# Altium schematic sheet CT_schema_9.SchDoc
size 385 x 278 mm
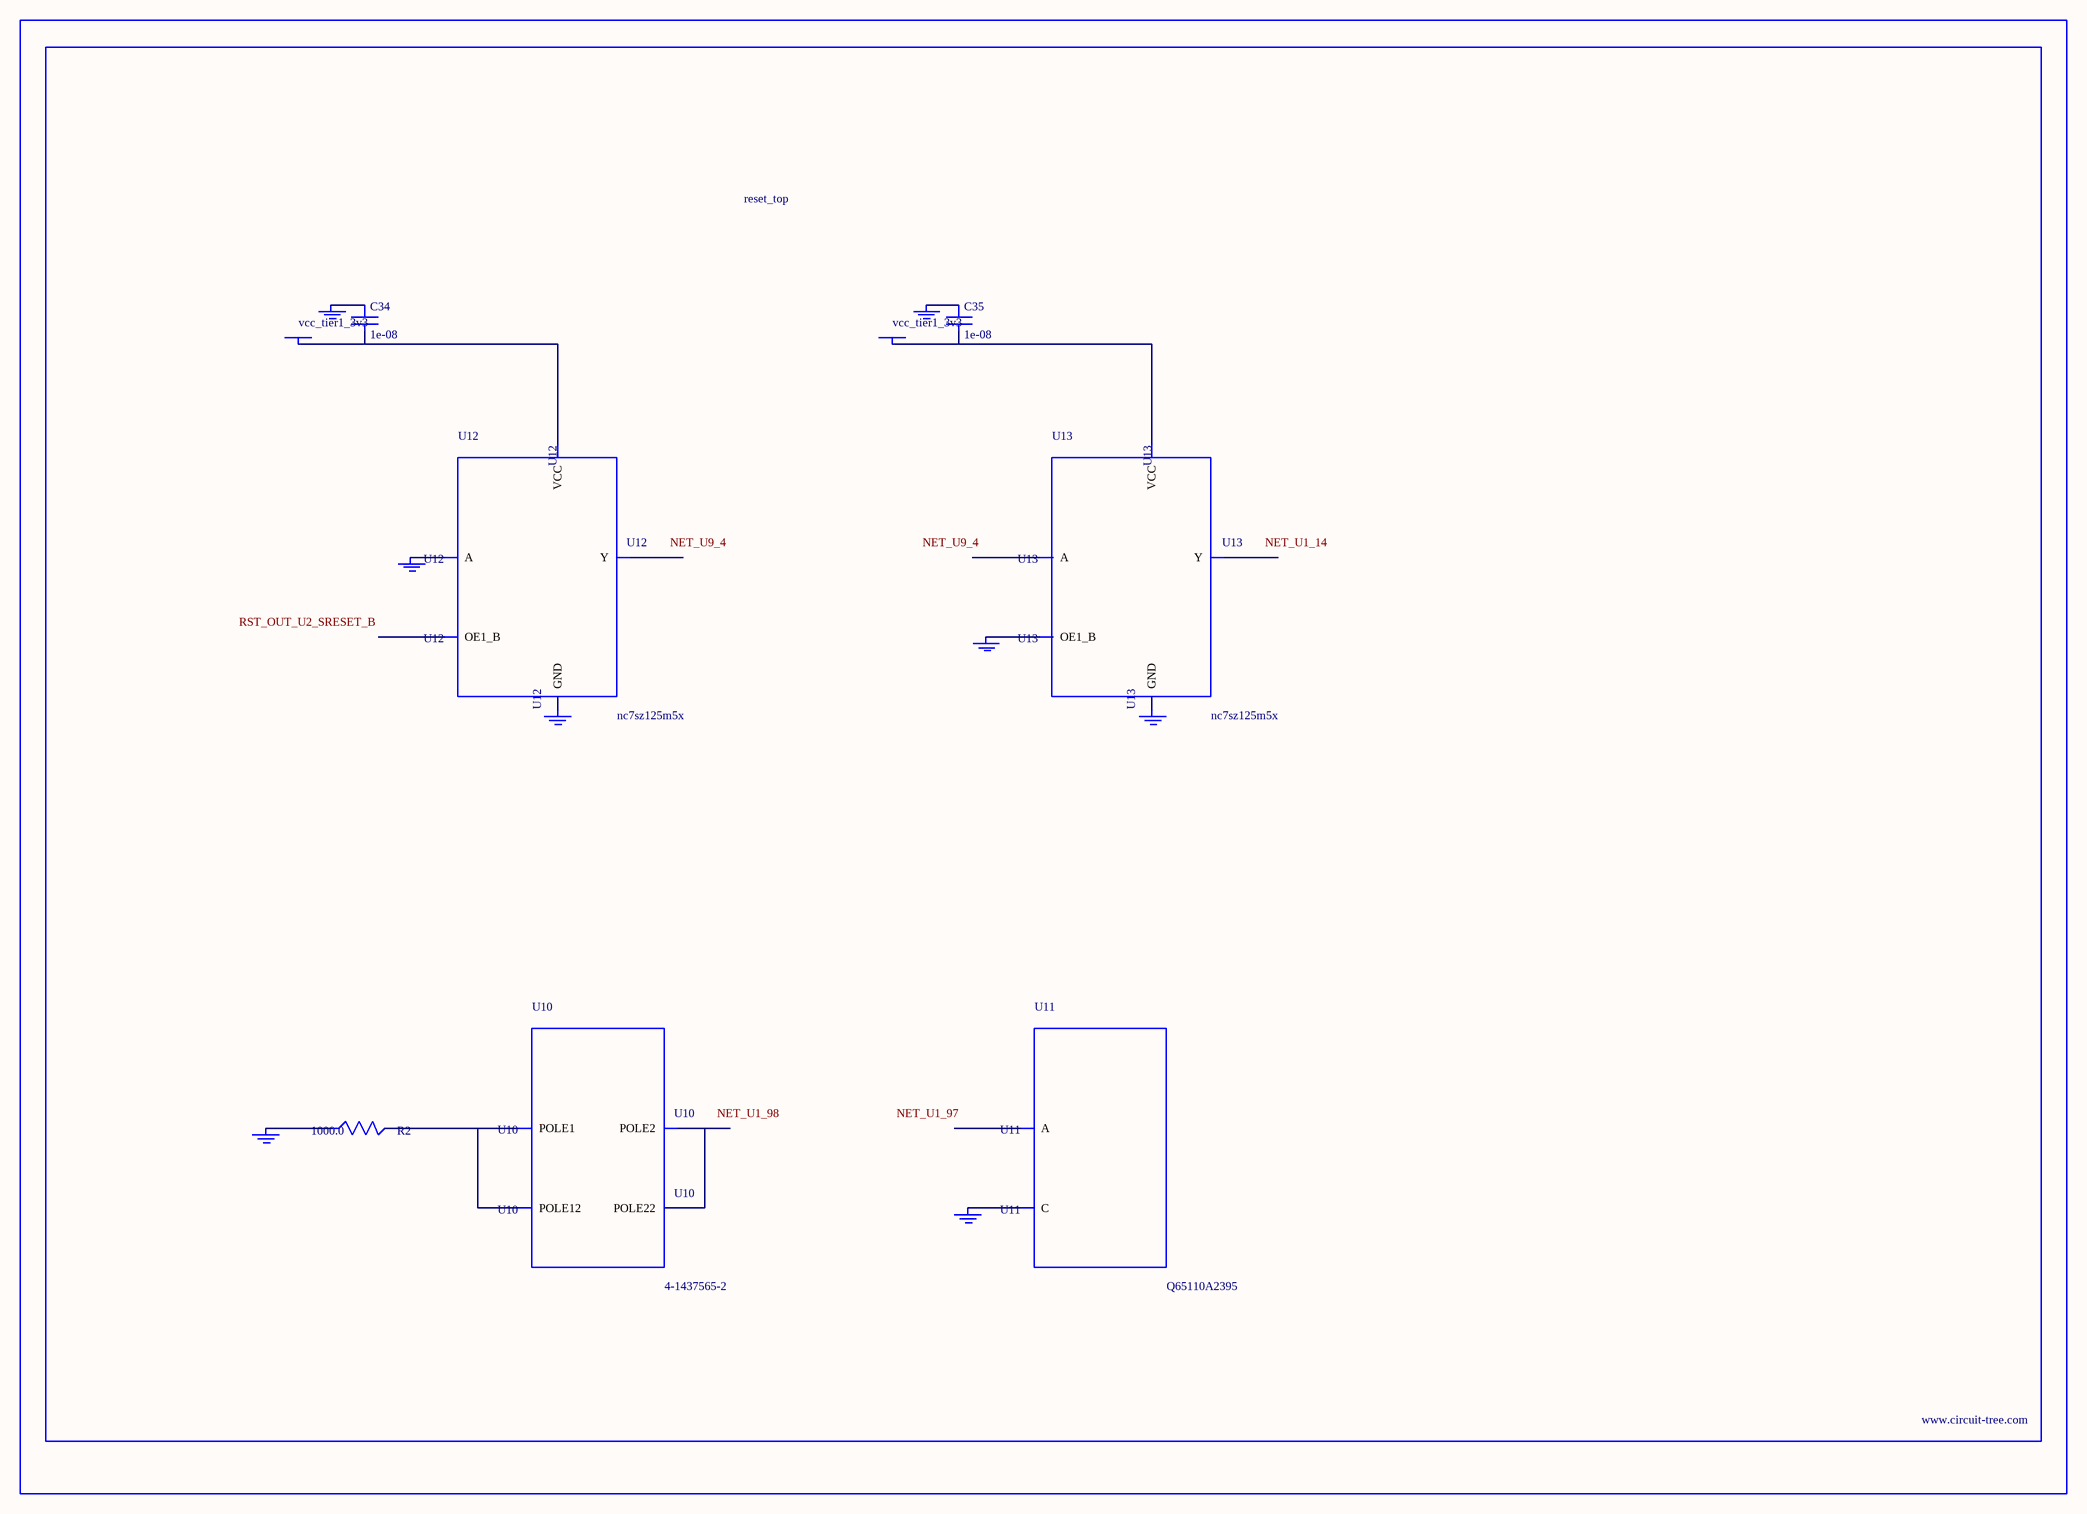
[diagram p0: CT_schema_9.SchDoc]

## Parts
BORDER8  (no value)
C34  1e-08  [C0402]
C35  1e-08  [C0402]
GND_INSTANCE_8_0  (no value)
GND_INSTANCE_8_1  (no value)
GND_INSTANCE_8_2  (no value)
GND_INSTANCE_8_3  (no value)
GND_INSTANCE_8_4  (no value)
GND_INSTANCE_8_5  (no value)
GND_INSTANCE_8_6  (no value)
GND_INSTANCE_8_7  (no value)
POWER_INSTANCE_8_0  vcc_tier1_3v3
POWER_INSTANCE_8_1  vcc_tier1_3v3
R2  1000.0  [R0603]
U10  4-1437565-2  [SW_4-1437565-2]
U11  Q65110A2395  [LGM67K-G1J2-24-Z]
U12  nc7sz125m5x  [NC7SZ125M5X]
U13  nc7sz125m5x  [NC7SZ125M5X]

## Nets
NetC34_1: C34.1 GND_INSTANCE_8_2.0(GND)
NetC34_2: C34.2 POWER_INSTANCE_8_0.0(PWR) U12.5(VCC)
NetC35_1: C35.1 GND_INSTANCE_8_5.0(GND)
NetC35_2: C35.2 POWER_INSTANCE_8_1.0(PWR) U13.5(VCC)
NetGND_INSTANCE_8_0_0: GND_INSTANCE_8_0.0(GND) R2.1
NetGND_INSTANCE_8_1_0: GND_INSTANCE_8_1.0(GND) U11.C
NetGND_INSTANCE_8_3_0: GND_INSTANCE_8_3.0(GND) U12.2(A)
NetGND_INSTANCE_8_4_0: GND_INSTANCE_8_4.0(GND) U12.3(GND)
NetGND_INSTANCE_8_6_0: GND_INSTANCE_8_6.0(GND) U13.1(OE1_B)
NetGND_INSTANCE_8_7_0: GND_INSTANCE_8_7.0(GND) U13.3(GND)
NetR2_2: R2.2 U10.1(POLE1) U10.2(POLE12)
NetU10_3: U10.3(POLE2) U10.4(POLE22)

Not connected (* = marked no-connect by the designer): U11 A; U12 1(OE1_B) 4(Y); U13 2(A) 4(Y)

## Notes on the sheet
- Labels drawn without touching a wire or pin: NET_U1_14, NET_U1_97, NET_U1_98, NET_U9_4, RST_OUT_U2_SRESET_B

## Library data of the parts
BORDER8 = BORDER_PAGE8
C34 C35 = C0402C103K3RAC
GND_INSTANCE_8_0-GND_INSTANCE_8_7 = GND
POWER_INSTANCE_8_0 POWER_INSTANCE_8_1 = PWR
R2 = RC0603JR-071KL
